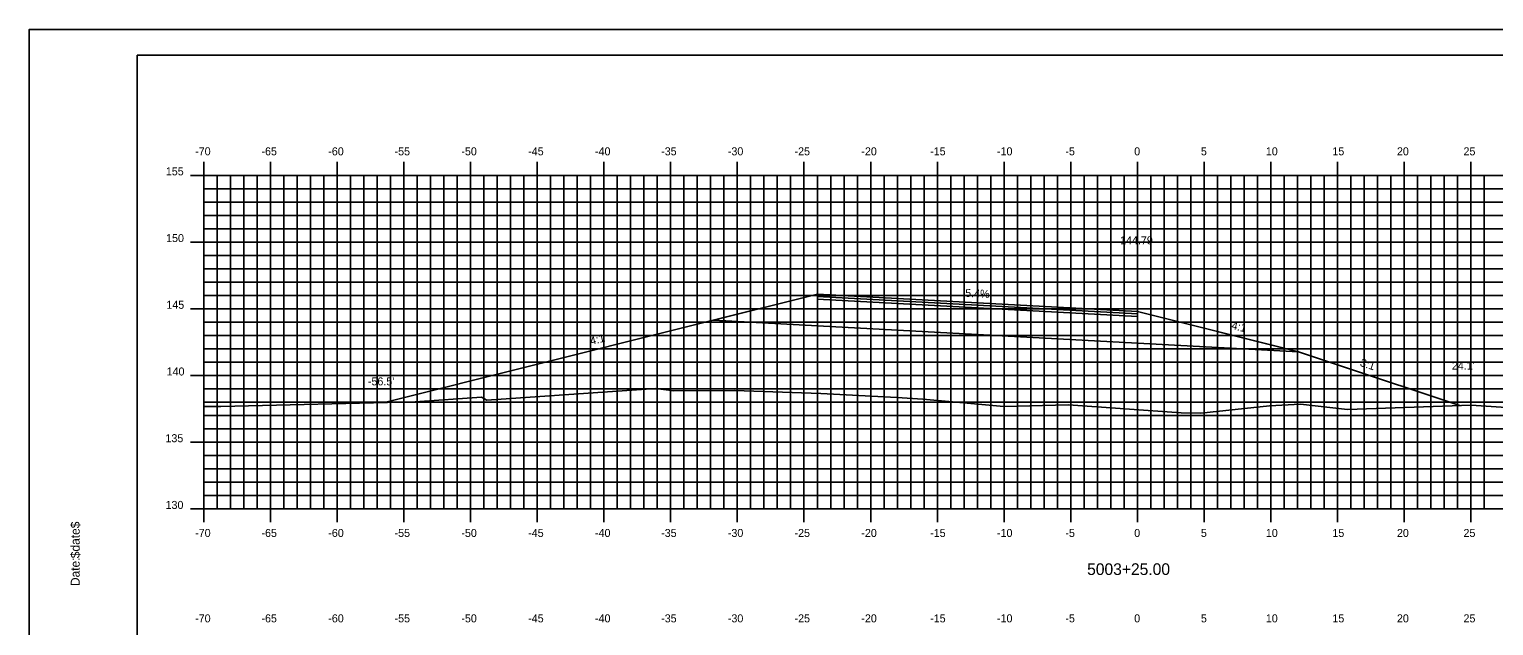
# Model space of a CAD drawing. Extents: x 851639 to 851810, y 365876 to 365986.
# Drawn here: x 851638.6 to 851748.4, y 365941.1 to 365985.8 of the extents above; entities that cross this region are included whole.
import ezdxf

# ---------------------------------------------------------------- set-up
doc = ezdxf.new("R2010")
doc.units = 0
for name, color, linetype in [('ANNOTATION', 7, 'Continuous'), ('BORDER', 7, 'Continuous'), ('D_Roadway_Centerline', 7, 'Continuous'), ('D_Roadway_Centerline_Text', 7, 'Continuous'), ('D_Roadway_Edge_TW', 7, 'Continuous'), ('D_Roadway_FinishedGrade', 7, 'Continuous'), ('D_Roadway_Pavement', 7, 'Continuous'), ('D_Roadway_SlopeLines', 7, 'Continuous'), ('D_Roadway_SubGrade', 7, 'Continuous'), ('D_Text_Standard', 7, 'Continuous'), ('H_V ANNOTATION', 7, 'Continuous'), ('MAJOR', 7, 'Continuous'), ('MINOR', 7, 'Continuous'), ('PLOT BOUNDARY', 7, 'Continuous'), ('S_Roadway_Centerline', 7, 'Continuous')]:
    doc.layers.add(name, color=color, linetype=linetype)

msp = doc.modelspace()

# ---------------------------------------------------------------- linework, layer by layer
at = {"layer": 'BORDER'}
msp.add_lwpolyline([(851646.66, 365878.83), (851806.66, 365878.83), (851806.66, 365983.83), (851646.66, 365983.83)], close=True, dxfattribs=at)
at = {"layer": 'D_Roadway_Centerline'}
msp.add_lwpolyline([(851665.19, 365957.8), (851687.65, 365963.42), (851697.65, 365965.92), (851721.65, 365964.63), (851733.73, 365961.61)], dxfattribs=at)
at = {"layer": 'D_Roadway_Edge_TW'}
msp.add_lwpolyline([(851697.65, 365965.92), (851721.65, 365964.63), (851721.65, 365964.46), (851697.65, 365965.75)], close=True, dxfattribs=at)
at = {"layer": 'D_Roadway_FinishedGrade'}
for p, q in [((851697.65, 365963.55), (851689.87, 365963.97)), ((851721.65, 365962.26), (851733.73, 365961.61))]:
    msp.add_line(p, q, dxfattribs=at)
msp.add_lwpolyline([(851733.73, 365961.61), (851736.73, 365960.61), (851745.82, 365957.58)], dxfattribs=at)
at = {"layer": 'D_Roadway_Pavement'}
msp.add_lwpolyline([(851697.65, 365965.75), (851721.65, 365964.46), (851721.65, 365964.26), (851697.65, 365965.55)], close=True, dxfattribs=at)
msp.add_lwpolyline([(851721.65, 365964.46), (851721.65, 365964.26)], dxfattribs=at)
msp.add_lwpolyline([(851721.65, 365964.46), (851721.65, 365964.26)], dxfattribs=at)
at = {"layer": 'D_Roadway_SlopeLines'}
for points in [[(851697.65, 365965.92), (851689.87, 365963.97)], [(851721.65, 365964.63), (851731.65, 365962.13), (851733.73, 365961.61)]]:
    msp.add_lwpolyline(points, dxfattribs=at)
at = {"layer": 'D_Roadway_SubGrade'}
for points in [[(851697.65, 365965.55), (851721.65, 365964.26)], [(851721.65, 365962.26), (851697.65, 365963.55)]]:
    msp.add_lwpolyline(points, dxfattribs=at)
at = {"layer": 'MAJOR'}
for p, q in [((851650.65, 365974.83), (851651.65, 365974.83)), ((851651.65, 365975.84), (851651.65, 365974.83)), ((851651.65, 365974.83), (851791.65, 365974.83)), ((851651.65, 365949.83), (851651.65, 365974.83)), ((851651.65, 365949.83), (851651.65, 365974.83)), ((851651.65, 365974.83), (851791.65, 365974.83)), ((851656.65, 365975.84), (851656.65, 365974.83)), ((851656.65, 365949.83), (851656.65, 365974.83)), ((851661.65, 365975.84), (851661.65, 365974.83)), ((851661.65, 365949.83), (851661.65, 365974.83)), ((851666.65, 365975.84), (851666.65, 365974.83)), ((851666.65, 365949.83), (851666.65, 365974.83)), ((851671.65, 365975.84), (851671.65, 365974.83)), ((851671.65, 365949.83), (851671.65, 365974.83)), ((851676.65, 365975.84), (851676.65, 365974.83)), ((851676.65, 365949.83), (851676.65, 365974.83)), ((851681.65, 365975.84), (851681.65, 365974.83)), ((851681.65, 365949.83), (851681.65, 365974.83)), ((851686.65, 365975.84), (851686.65, 365974.83)), ((851686.65, 365949.83), (851686.65, 365974.83)), ((851691.65, 365975.84), (851691.65, 365974.83)), ((851691.65, 365949.83), (851691.65, 365974.83)), ((851696.65, 365975.84), (851696.65, 365974.83)), ((851696.65, 365949.83), (851696.65, 365974.83)), ((851701.65, 365975.84), (851701.65, 365974.83)), ((851701.65, 365949.83), (851701.65, 365974.83)), ((851706.65, 365975.84), (851706.65, 365974.83)), ((851706.65, 365949.83), (851706.65, 365974.83)), ((851711.65, 365975.84), (851711.65, 365974.83)), ((851711.65, 365949.83), (851711.65, 365974.83)), ((851716.65, 365975.84), (851716.65, 365974.83)), ((851716.65, 365949.83), (851716.65, 365974.83)), ((851721.65, 365975.84), (851721.65, 365974.83)), ((851721.65, 365949.83), (851721.65, 365974.83)), ((851726.65, 365975.84), (851726.65, 365974.83)), ((851726.65, 365949.83), (851726.65, 365974.83)), ((851731.65, 365975.84), (851731.65, 365974.83)), ((851731.65, 365949.83), (851731.65, 365974.83)), ((851736.65, 365975.84), (851736.65, 365974.83)), ((851736.65, 365949.83), (851736.65, 365974.83)), ((851741.65, 365975.84), (851741.65, 365974.83)), ((851741.65, 365949.83), (851741.65, 365974.83)), ((851746.65, 365975.84), (851746.65, 365974.83)), ((851746.65, 365949.83), (851746.65, 365974.83)), ((851650.65, 365969.83), (851651.65, 365969.83)), ((851651.65, 365969.83), (851791.65, 365969.83)), ((851650.65, 365964.83), (851651.65, 365964.83)), ((851651.65, 365964.83), (851791.65, 365964.83)), ((851650.65, 365959.83), (851651.65, 365959.83)), ((851651.65, 365959.83), (851791.65, 365959.83)), ((851650.65, 365954.83), (851651.65, 365954.83)), ((851651.65, 365954.83), (851791.65, 365954.83)), ((851650.65, 365949.83), (851651.65, 365949.83)), ((851651.65, 365949.83), (851791.65, 365949.83)), ((851651.65, 365949.83), (851791.65, 365949.83)), ((851651.65, 365948.83), (851651.65, 365949.83)), ((851656.65, 365948.83), (851656.65, 365949.83)), ((851661.65, 365948.83), (851661.65, 365949.83)), ((851666.65, 365948.83), (851666.65, 365949.83)), ((851671.65, 365948.83), (851671.65, 365949.83)), ((851676.65, 365948.83), (851676.65, 365949.83)), ((851681.65, 365948.83), (851681.65, 365949.83)), ((851686.65, 365948.83), (851686.65, 365949.83)), ((851691.65, 365948.83), (851691.65, 365949.83)), ((851696.65, 365948.83), (851696.65, 365949.83)), ((851701.65, 365948.83), (851701.65, 365949.83)), ((851706.65, 365948.83), (851706.65, 365949.83)), ((851711.65, 365948.83), (851711.65, 365949.83)), ((851716.65, 365948.83), (851716.65, 365949.83)), ((851721.65, 365948.83), (851721.65, 365949.83)), ((851726.65, 365948.83), (851726.65, 365949.83)), ((851731.65, 365948.83), (851731.65, 365949.83)), ((851736.65, 365948.83), (851736.65, 365949.83)), ((851741.65, 365948.83), (851741.65, 365949.83)), ((851746.65, 365948.83), (851746.65, 365949.83))]:
    msp.add_line(p, q, dxfattribs=at)
at = {"layer": 'MINOR'}
for p, q in [((851652.65, 365949.83), (851652.65, 365974.83)), ((851653.65, 365949.83), (851653.65, 365974.83)), ((851654.65, 365949.83), (851654.65, 365974.83)), ((851655.65, 365949.83), (851655.65, 365974.83)), ((851657.65, 365949.83), (851657.65, 365974.83)), ((851658.65, 365949.83), (851658.65, 365974.83)), ((851659.65, 365949.83), (851659.65, 365974.83)), ((851660.65, 365949.83), (851660.65, 365974.83)), ((851662.65, 365949.83), (851662.65, 365974.83)), ((851663.65, 365949.83), (851663.65, 365974.83)), ((851664.65, 365949.83), (851664.65, 365974.83)), ((851665.65, 365949.83), (851665.65, 365974.83)), ((851667.65, 365949.83), (851667.65, 365974.83)), ((851668.65, 365949.83), (851668.65, 365974.83)), ((851669.65, 365949.83), (851669.65, 365974.83)), ((851670.65, 365949.83), (851670.65, 365974.83)), ((851672.65, 365949.83), (851672.65, 365974.83)), ((851673.65, 365949.83), (851673.65, 365974.83)), ((851674.65, 365949.83), (851674.65, 365974.83)), ((851675.65, 365949.83), (851675.65, 365974.83)), ((851677.65, 365949.83), (851677.65, 365974.83)), ((851678.65, 365949.83), (851678.65, 365974.83)), ((851679.65, 365949.83), (851679.65, 365974.83)), ((851680.65, 365949.83), (851680.65, 365974.83)), ((851682.65, 365949.83), (851682.65, 365974.83)), ((851683.65, 365949.83), (851683.65, 365974.83)), ((851684.65, 365949.83), (851684.65, 365974.83)), ((851685.65, 365949.83), (851685.65, 365974.83)), ((851687.65, 365949.83), (851687.65, 365974.83)), ((851688.65, 365949.83), (851688.65, 365974.83)), ((851689.65, 365949.83), (851689.65, 365974.83)), ((851690.65, 365949.83), (851690.65, 365974.83)), ((851692.65, 365949.83), (851692.65, 365974.83)), ((851693.65, 365949.83), (851693.65, 365974.83)), ((851694.65, 365949.83), (851694.65, 365974.83)), ((851695.65, 365949.83), (851695.65, 365974.83)), ((851697.65, 365949.83), (851697.65, 365974.83)), ((851698.65, 365949.83), (851698.65, 365974.83)), ((851699.65, 365949.83), (851699.65, 365974.83)), ((851700.65, 365949.83), (851700.65, 365974.83)), ((851702.65, 365949.83), (851702.65, 365974.83)), ((851703.65, 365949.83), (851703.65, 365974.83)), ((851704.65, 365949.83), (851704.65, 365974.83)), ((851705.65, 365949.83), (851705.65, 365974.83)), ((851707.65, 365949.83), (851707.65, 365974.83)), ((851708.65, 365949.83), (851708.65, 365974.83)), ((851709.65, 365949.83), (851709.65, 365974.83)), ((851710.65, 365949.83), (851710.65, 365974.83)), ((851712.65, 365949.83), (851712.65, 365974.83)), ((851713.65, 365949.83), (851713.65, 365974.83)), ((851714.65, 365949.83), (851714.65, 365974.83)), ((851715.65, 365949.83), (851715.65, 365974.83)), ((851717.65, 365949.83), (851717.65, 365974.83)), ((851718.65, 365949.83), (851718.65, 365974.83)), ((851719.65, 365949.83), (851719.65, 365974.83)), ((851720.65, 365949.83), (851720.65, 365974.83)), ((851722.65, 365949.83), (851722.65, 365974.83)), ((851723.65, 365949.83), (851723.65, 365974.83)), ((851724.65, 365949.83), (851724.65, 365974.83)), ((851725.65, 365949.83), (851725.65, 365974.83)), ((851727.65, 365949.83), (851727.65, 365974.83)), ((851728.65, 365949.83), (851728.65, 365974.83)), ((851729.65, 365949.83), (851729.65, 365974.83)), ((851730.65, 365949.83), (851730.65, 365974.83)), ((851732.65, 365949.83), (851732.65, 365974.83)), ((851733.65, 365949.83), (851733.65, 365974.83)), ((851734.65, 365949.83), (851734.65, 365974.83)), ((851735.65, 365949.83), (851735.65, 365974.83)), ((851737.65, 365949.83), (851737.65, 365974.83)), ((851738.65, 365949.83), (851738.65, 365974.83)), ((851739.65, 365949.83), (851739.65, 365974.83)), ((851740.65, 365949.83), (851740.65, 365974.83)), ((851742.65, 365949.83), (851742.65, 365974.83)), ((851743.65, 365949.83), (851743.65, 365974.83)), ((851744.65, 365949.83), (851744.65, 365974.83)), ((851745.65, 365949.83), (851745.65, 365974.83)), ((851747.65, 365949.83), (851747.65, 365974.83)), ((851651.65, 365973.83), (851791.65, 365973.83)), ((851651.65, 365973.83), (851652.66, 365973.83)), ((851651.65, 365972.83), (851791.65, 365972.83)), ((851651.65, 365972.83), (851652.66, 365972.83)), ((851651.65, 365971.83), (851791.65, 365971.83)), ((851651.65, 365971.83), (851652.66, 365971.83)), ((851651.65, 365970.83), (851791.65, 365970.83)), ((851651.65, 365970.83), (851652.66, 365970.83)), ((851651.65, 365968.83), (851791.65, 365968.83)), ((851651.65, 365968.83), (851652.66, 365968.83)), ((851651.65, 365967.83), (851791.65, 365967.83)), ((851651.65, 365967.83), (851652.66, 365967.83)), ((851651.65, 365966.83), (851791.65, 365966.83)), ((851651.65, 365966.83), (851652.66, 365966.83)), ((851651.65, 365965.83), (851791.65, 365965.83)), ((851651.65, 365965.83), (851652.66, 365965.83)), ((851651.65, 365963.83), (851791.65, 365963.83)), ((851651.65, 365963.83), (851652.66, 365963.83)), ((851651.65, 365962.83), (851791.65, 365962.83)), ((851651.65, 365962.83), (851652.66, 365962.83)), ((851651.65, 365961.83), (851791.65, 365961.83)), ((851651.65, 365961.83), (851652.66, 365961.83)), ((851651.65, 365960.83), (851791.65, 365960.83)), ((851651.65, 365960.83), (851652.66, 365960.83)), ((851651.65, 365958.83), (851791.65, 365958.83)), ((851651.65, 365958.83), (851652.66, 365958.83)), ((851651.65, 365957.83), (851791.65, 365957.83)), ((851651.65, 365957.83), (851652.66, 365957.83)), ((851651.65, 365956.83), (851791.65, 365956.83)), ((851651.65, 365956.83), (851652.66, 365956.83)), ((851651.65, 365955.83), (851791.65, 365955.83)), ((851651.65, 365955.83), (851652.66, 365955.83)), ((851651.65, 365953.83), (851791.65, 365953.83)), ((851651.65, 365953.83), (851652.66, 365953.83)), ((851651.65, 365952.83), (851791.65, 365952.83)), ((851651.65, 365952.83), (851652.66, 365952.83)), ((851651.65, 365951.83), (851791.65, 365951.83)), ((851651.65, 365951.83), (851652.66, 365951.83)), ((851651.65, 365950.83), (851791.65, 365950.83)), ((851651.65, 365950.83), (851652.66, 365950.83))]:
    msp.add_line(p, q, dxfattribs=at)
at = {"layer": 'PLOT BOUNDARY'}
msp.add_lwpolyline([(851638.56, 365875.77), (851808.56, 365875.77), (851808.56, 365985.77), (851638.56, 365985.77)], close=True, dxfattribs=at)
at = {"layer": 'S_Roadway_Centerline'}
msp.add_lwpolyline([(851651.65, 365957.5), (851651.68, 365957.51), (851652.93, 365957.5), (851667.5, 365957.86), (851672.48, 365958.21), (851672.86, 365957.97), (851685.54, 365958.86), (851686.89, 365958.68), (851691.44, 365958.71), (851697.91, 365958.49), (851703.61, 365958.17), (851705.55, 365958.06), (851707.52, 365957.89), (851711.64, 365957.5), (851716.49, 365957.64), (851724.93, 365957.04), (851726.41, 365957.01), (851731.56, 365957.56), (851733.87, 365957.69), (851737.39, 365957.27), (851746.68, 365957.6), (851751.58, 365957.29)], dxfattribs=at)

# ---------------------------------------------------------------- texts
at = {"layer": 'ANNOTATION'}
for s, rotation, p in [('5.4%', 356.909, (851708.72, 365965.73)), ('4:1', 345.9638, (851728.66, 365963.33)), ('4:1', 14.0362, (851680.69, 365962.11)), ('-3:1', 341.9333, (851738.04, 365960.64))]:
    msp.add_text(s, height=0.6, rotation=rotation, dxfattribs=at).set_placement(p)
at = {"layer": 'BORDER'}
for s, p in [('$date$', (851642.34, 365946.14)), ('Date:', (851642.34, 365944.05))]:
    msp.add_text(s, height=0.67, rotation=90, dxfattribs=at).set_placement(p)
at = {"layer": 'D_Roadway_Centerline_Text'}
msp.add_text('144.79', height=0.6, dxfattribs=at).set_placement((851720.35, 365969.66))
at = {"layer": 'D_Text_Standard'}
for s, p in [("24.1'", (851745.23, 365960.27)), ("-56.5'", (851663.95, 365959.09))]:
    msp.add_text(s, height=0.6, dxfattribs=at).set_placement(p)
at = {"layer": 'H_V ANNOTATION'}
for s, height, p in [('-70', 0.6, (851651, 365976.33)), ('-65', 0.6, (851655.97, 365976.33)), ('-60', 0.6, (851660.98, 365976.33)), ('-55', 0.6, (851665.95, 365976.33)), ('-50', 0.6, (851670.96, 365976.33)), ('-45', 0.6, (851675.97, 365976.33)), ('-40', 0.6, (851680.98, 365976.33)), ('-35', 0.6, (851685.94, 365976.33)), ('-30', 0.6, (851690.94, 365976.33)), ('-25', 0.6, (851695.94, 365976.33)), ('-20', 0.6, (851700.95, 365976.33)), ('-15', 0.6, (851706.11, 365976.33)), ('-10', 0.6, (851711.12, 365976.33)), ('-5', 0.6, (851716.25, 365976.33)), ('0', 0.6, (851721.41, 365976.33)), ('5', 0.6, (851726.41, 365976.33)), ('10', 0.6, (851731.28, 365976.33)), ('15', 0.6, (851736.27, 365976.33)), ('20', 0.6, (851741.11, 365976.33)), ('25', 0.6, (851746.1, 365976.33)), ('155', 0.6, (851648.8, 365974.83)), ('150', 0.6, (851648.82, 365969.83)), ('145', 0.6, (851648.84, 365964.83)), ('140', 0.6, (851648.86, 365959.83)), ('135', 0.6, (851648.77, 365954.83)), ('130', 0.6, (851648.78, 365949.83)), ('-70', 0.6, (851651, 365947.73)), ('-65', 0.6, (851655.97, 365947.73)), ('-60', 0.6, (851660.98, 365947.73)), ('-55', 0.6, (851665.95, 365947.73)), ('-50', 0.6, (851670.96, 365947.73)), ('-45', 0.6, (851675.97, 365947.73)), ('-40', 0.6, (851680.98, 365947.73)), ('-35', 0.6, (851685.94, 365947.73)), ('-30', 0.6, (851690.94, 365947.73)), ('-25', 0.6, (851695.94, 365947.73)), ('-20', 0.6, (851700.95, 365947.73)), ('-15', 0.6, (851706.11, 365947.73)), ('-10', 0.6, (851711.12, 365947.73)), ('-5', 0.6, (851716.25, 365947.73)), ('0', 0.6, (851721.41, 365947.73)), ('5', 0.6, (851726.41, 365947.73)), ('10', 0.6, (851731.28, 365947.73)), ('15', 0.6, (851736.27, 365947.73)), ('20', 0.6, (851741.11, 365947.73)), ('25', 0.6, (851746.1, 365947.73)), ('5003+25.00', 0.875, (851717.88, 365944.88)), ('-70', 0.6, (851651, 365941.33)), ('-65', 0.6, (851655.97, 365941.33)), ('-60', 0.6, (851660.98, 365941.33)), ('-55', 0.6, (851665.95, 365941.33)), ('-50', 0.6, (851670.96, 365941.33)), ('-45', 0.6, (851675.97, 365941.33)), ('-40', 0.6, (851680.98, 365941.33)), ('-35', 0.6, (851685.94, 365941.33)), ('-30', 0.6, (851690.94, 365941.33)), ('-25', 0.6, (851695.94, 365941.33)), ('-20', 0.6, (851700.95, 365941.33)), ('-15', 0.6, (851706.11, 365941.33)), ('-10', 0.6, (851711.12, 365941.33)), ('-5', 0.6, (851716.25, 365941.33)), ('0', 0.6, (851721.41, 365941.33)), ('5', 0.6, (851726.41, 365941.33)), ('10', 0.6, (851731.28, 365941.33)), ('15', 0.6, (851736.27, 365941.33)), ('20', 0.6, (851741.11, 365941.33)), ('25', 0.6, (851746.1, 365941.33))]:
    msp.add_text(s, height=height, dxfattribs=at).set_placement(p)
at = {"layer": 'MAJOR'}
msp.add_text('-', height=0.006, dxfattribs=at).set_placement((851651.65, 365949.83))

doc.saveas('drawing.dxf')
